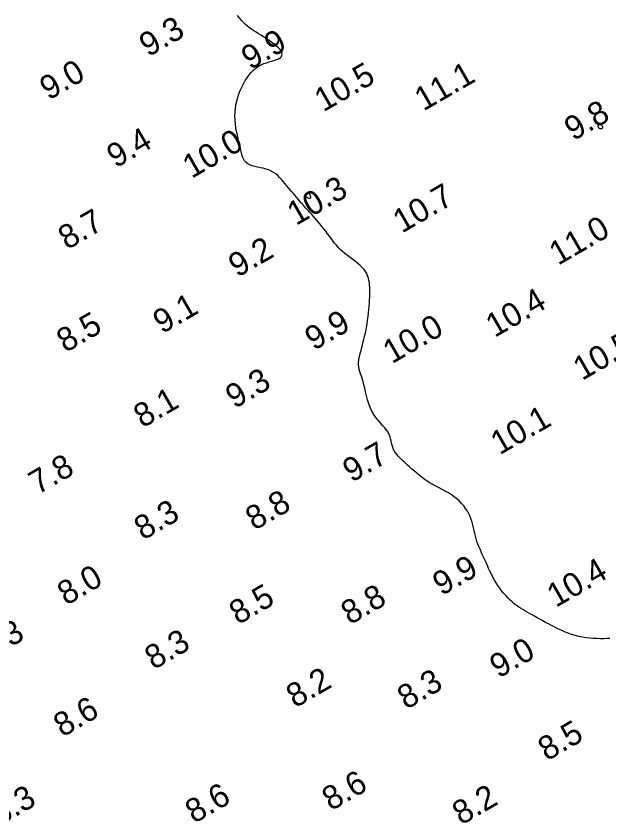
# Model space of a CAD drawing. Extents: x 3024098 to 3056816, y 418252 to 509144.
# Drawn here: x 3029994.4 to 3030119.4, y 418627.8 to 418798.2 of the extents above; entities that cross this region are included whole.
import ezdxf

# ---------------------------------------------------------------- set-up
doc = ezdxf.new("R2010")
doc.units = 0
doc.layers.add('V-CHAN-CONT-EL10', color=7, linetype='Continuous')
doc.layers.add('V-TOPO-SOUN-0911', color=7, linetype='Continuous')

msp = doc.modelspace()

# ---------------------------------------------------------------- linework, layer by layer
at = {"layer": 'V-CHAN-CONT-EL10'}
msp.add_lwpolyline([(3030119.56, 418666.92), (3030118.96, 418666.9), (3030118.31, 418666.89), (3030117.62, 418666.89), (3030116.9, 418666.9), (3030116.15, 418666.93), (3030115.39, 418666.99), (3030114.61, 418667.08), (3030113.82, 418667.19), (3030113.04, 418667.35), (3030112.27, 418667.55), (3030111.52, 418667.78), (3030110.77, 418668.05), (3030110.04, 418668.34), (3030109.33, 418668.66), (3030108.63, 418668.98), (3030107.95, 418669.32), (3030107.29, 418669.66), (3030106.64, 418669.99), (3030106.02, 418670.33), (3030105.42, 418670.66), (3030104.83, 418670.98), (3030104.26, 418671.29), (3030103.71, 418671.6), (3030103.18, 418671.9), (3030102.67, 418672.19), (3030102.17, 418672.48), (3030101.69, 418672.75), (3030101.21, 418673.03), (3030100.75, 418673.32), (3030100.3, 418673.61), (3030099.85, 418673.93), (3030099.4, 418674.27), (3030098.96, 418674.65), (3030098.51, 418675.05), (3030098.06, 418675.49), (3030097.62, 418675.96), (3030097.19, 418676.46), (3030096.76, 418676.98), (3030096.36, 418677.52), (3030095.96, 418678.09), (3030095.59, 418678.67), (3030095.25, 418679.26), (3030094.92, 418679.87), (3030094.61, 418680.48), (3030094.31, 418681.1), (3030094.03, 418681.71), (3030093.76, 418682.32), (3030093.49, 418682.92), (3030093.23, 418683.51), (3030092.96, 418684.09), (3030092.7, 418684.65), (3030092.45, 418685.2), (3030092.21, 418685.75), (3030091.97, 418686.3), (3030091.76, 418686.84), (3030091.56, 418687.4), (3030091.39, 418687.96), (3030091.23, 418688.53), (3030091.1, 418689.1), (3030090.97, 418689.69), (3030090.83, 418690.28), (3030090.69, 418690.87), (3030090.53, 418691.46), (3030090.35, 418692.05), (3030090.12, 418692.64), (3030089.85, 418693.22), (3030089.54, 418693.78), (3030089.18, 418694.34), (3030088.78, 418694.88), (3030088.34, 418695.4), (3030087.86, 418695.9), (3030087.34, 418696.37), (3030086.78, 418696.82), (3030086.18, 418697.23), (3030085.55, 418697.62), (3030084.9, 418697.98), (3030084.24, 418698.34), (3030083.58, 418698.69), (3030082.92, 418699.03), (3030082.27, 418699.38), (3030081.64, 418699.74), (3030081.04, 418700.12), (3030080.47, 418700.51), (3030079.93, 418700.92), (3030079.39, 418701.34), (3030078.88, 418701.77), (3030078.37, 418702.2), (3030077.86, 418702.65), (3030077.35, 418703.1), (3030076.85, 418703.55), (3030076.34, 418704.01), (3030075.86, 418704.47), (3030075.39, 418704.93), (3030074.97, 418705.39), (3030074.58, 418705.85), (3030074.26, 418706.31), (3030073.99, 418706.76), (3030073.8, 418707.22), (3030073.66, 418707.67), (3030073.55, 418708.12), (3030073.46, 418708.57), (3030073.36, 418709.03), (3030073.24, 418709.48), (3030073.07, 418709.94), (3030072.83, 418710.41), (3030072.51, 418710.88), (3030072.13, 418711.36), (3030071.69, 418711.86), (3030071.22, 418712.39), (3030070.74, 418712.95), (3030070.27, 418713.55), (3030069.82, 418714.19), (3030069.41, 418714.89), (3030069.06, 418715.64), (3030068.76, 418716.44), (3030068.5, 418717.26), (3030068.28, 418718.09), (3030068.09, 418718.91), (3030067.91, 418719.69), (3030067.74, 418720.44), (3030067.57, 418721.12), (3030067.39, 418721.72), (3030067.21, 418722.26), (3030067.04, 418722.76), (3030066.89, 418723.23), (3030066.77, 418723.68), (3030066.68, 418724.15), (3030066.63, 418724.63), (3030066.63, 418725.16), (3030066.69, 418725.74), (3030066.81, 418726.37), (3030066.96, 418727.04), (3030067.14, 418727.76), (3030067.34, 418728.51), (3030067.54, 418729.28), (3030067.75, 418730.07), (3030067.94, 418730.87), (3030068.12, 418731.68), (3030068.27, 418732.49), (3030068.4, 418733.29), (3030068.52, 418734.08), (3030068.62, 418734.86), (3030068.7, 418735.61), (3030068.78, 418736.33), (3030068.84, 418737.02), (3030068.9, 418737.67), (3030068.94, 418738.29), (3030068.98, 418738.88), (3030069.01, 418739.43), (3030069.02, 418739.97), (3030069.01, 418740.49), (3030068.99, 418740.99), (3030068.95, 418741.48), (3030068.89, 418741.97), (3030068.8, 418742.45), (3030068.68, 418742.93), (3030068.52, 418743.4), (3030068.32, 418743.86), (3030068.07, 418744.31), (3030067.76, 418744.75), (3030067.39, 418745.19), (3030066.96, 418745.61), (3030066.47, 418746.03), (3030065.94, 418746.44), (3030065.39, 418746.84), (3030064.83, 418747.25), (3030064.27, 418747.67), (3030063.73, 418748.08), (3030063.22, 418748.51), (3030062.75, 418748.95), (3030062.32, 418749.39), (3030061.93, 418749.85), (3030061.55, 418750.32), (3030061.19, 418750.8), (3030060.83, 418751.28), (3030060.46, 418751.78), (3030060.09, 418752.29), (3030059.7, 418752.8), (3030059.29, 418753.31), (3030058.87, 418753.83), (3030058.44, 418754.35), (3030058.01, 418754.86), (3030057.58, 418755.35), (3030057.16, 418755.84), (3030056.75, 418756.31), (3030056.35, 418756.76), (3030055.97, 418757.19), (3030055.6, 418757.61), (3030055.23, 418758.01), (3030054.88, 418758.41), (3030054.53, 418758.8), (3030054.19, 418759.2), (3030053.85, 418759.59), (3030053.51, 418759.99), (3030053.17, 418760.4), (3030052.83, 418760.81), (3030052.49, 418761.22), (3030052.15, 418761.64), (3030051.8, 418762.05), (3030051.45, 418762.48), (3030051.1, 418762.9), (3030050.74, 418763.32), (3030050.37, 418763.74), (3030049.98, 418764.14), (3030049.58, 418764.53), (3030049.16, 418764.89), (3030048.7, 418765.21), (3030048.21, 418765.5), (3030047.69, 418765.74), (3030047.12, 418765.93), (3030046.53, 418766.08), (3030045.93, 418766.21), (3030045.33, 418766.33), (3030044.74, 418766.45), (3030044.19, 418766.6), (3030043.69, 418766.78), (3030043.26, 418767.01), (3030042.89, 418767.29), (3030042.6, 418767.64), (3030042.36, 418768.05), (3030042.16, 418768.51), (3030041.99, 418769.02), (3030041.84, 418769.59), (3030041.7, 418770.2), (3030041.56, 418770.85), (3030041.4, 418771.55), (3030041.23, 418772.28), (3030041.06, 418773.04), (3030040.91, 418773.83), (3030040.77, 418774.63), (3030040.66, 418775.45), (3030040.58, 418776.26), (3030040.55, 418777.08), (3030040.57, 418777.89), (3030040.64, 418778.69), (3030040.76, 418779.48), (3030040.92, 418780.26), (3030041.13, 418781.03), (3030041.38, 418781.78), (3030041.66, 418782.51), (3030041.98, 418783.22), (3030042.33, 418783.9), (3030042.72, 418784.56), (3030043.13, 418785.19), (3030043.57, 418785.78), (3030044.03, 418786.32), (3030044.52, 418786.81), (3030045.03, 418787.24), (3030045.56, 418787.61), (3030046.1, 418787.91), (3030046.65, 418788.15), (3030047.2, 418788.35), (3030047.74, 418788.51), (3030048.25, 418788.65), (3030048.73, 418788.79), (3030049.17, 418788.92), (3030049.56, 418789.06), (3030049.89, 418789.23), (3030050.15, 418789.43), (3030050.34, 418789.65), (3030050.46, 418789.89), (3030050.49, 418790.16), (3030050.44, 418790.45), (3030050.3, 418790.77), (3030050.07, 418791.11), (3030049.74, 418791.47), (3030049.32, 418791.85), (3030048.85, 418792.24), (3030048.32, 418792.63), (3030047.75, 418793.03), (3030047.18, 418793.41), (3030046.6, 418793.78), (3030046.04, 418794.13), (3030045.51, 418794.46), (3030045.01, 418794.77), (3030044.53, 418795.07), (3030044.08, 418795.38), (3030043.64, 418795.69), (3030043.21, 418796.03), (3030042.79, 418796.41), (3030042.38, 418796.82), (3030041.96, 418797.28), (3030041.54, 418797.79), (3030041.12, 418798.33)], dxfattribs=at)
for points in [[(3030117.82, 418774.46), (3030117.84, 418774.46), (3030117.85, 418774.47), (3030117.87, 418774.47), (3030117.89, 418774.47), (3030117.92, 418774.48), (3030117.94, 418774.49), (3030117.96, 418774.51), (3030117.99, 418774.53), (3030118.01, 418774.55), (3030118.04, 418774.58), (3030118.06, 418774.61), (3030118.08, 418774.64), (3030118.09, 418774.67), (3030118.1, 418774.71), (3030118.1, 418774.74), (3030118.09, 418774.78), (3030118.07, 418774.82), (3030118.04, 418774.86), (3030118.02, 418774.9), (3030117.98, 418774.94), (3030117.95, 418774.99), (3030117.92, 418775.04), (3030117.88, 418775.1), (3030117.85, 418775.16), (3030117.82, 418775.23), (3030117.79, 418775.29), (3030117.76, 418775.35), (3030117.73, 418775.41), (3030117.7, 418775.46), (3030117.67, 418775.5), (3030117.63, 418775.53), (3030117.59, 418775.54), (3030117.55, 418775.54), (3030117.5, 418775.53), (3030117.46, 418775.51), (3030117.41, 418775.49), (3030117.37, 418775.45), (3030117.32, 418775.41), (3030117.28, 418775.37), (3030117.24, 418775.33), (3030117.2, 418775.28), (3030117.17, 418775.23), (3030117.14, 418775.18), (3030117.12, 418775.13), (3030117.1, 418775.07), (3030117.09, 418775.02), (3030117.08, 418774.96), (3030117.08, 418774.9), (3030117.1, 418774.85), (3030117.11, 418774.79), (3030117.14, 418774.73), (3030117.16, 418774.68), (3030117.19, 418774.64), (3030117.23, 418774.6), (3030117.27, 418774.56), (3030117.31, 418774.54), (3030117.36, 418774.52), (3030117.4, 418774.5), (3030117.45, 418774.49), (3030117.5, 418774.48), (3030117.54, 418774.48), (3030117.58, 418774.48), (3030117.62, 418774.48), (3030117.65, 418774.48), (3030117.68, 418774.48), (3030117.71, 418774.48), (3030117.73, 418774.47), (3030117.75, 418774.47), (3030117.77, 418774.47), (3030117.78, 418774.47), (3030117.8, 418774.47)], [(3030056.49, 418759.85), (3030056.52, 418759.91), (3030056.53, 418759.98), (3030056.52, 418760.06), (3030056.51, 418760.14), (3030056.48, 418760.23), (3030056.45, 418760.31), (3030056.42, 418760.38), (3030056.38, 418760.45), (3030056.35, 418760.51), (3030056.31, 418760.57), (3030056.27, 418760.61), (3030056.23, 418760.65), (3030056.19, 418760.69), (3030056.14, 418760.73), (3030056.09, 418760.76), (3030056.03, 418760.79), (3030055.96, 418760.82), (3030055.9, 418760.84), (3030055.83, 418760.85), (3030055.76, 418760.85), (3030055.7, 418760.85), (3030055.64, 418760.82), (3030055.59, 418760.78), (3030055.54, 418760.72), (3030055.51, 418760.64), (3030055.49, 418760.55), (3030055.48, 418760.45), (3030055.49, 418760.35), (3030055.51, 418760.25), (3030055.56, 418760.15), (3030055.62, 418760.06), (3030055.71, 418759.98), (3030055.81, 418759.91), (3030055.92, 418759.85), (3030056.04, 418759.81), (3030056.16, 418759.79), (3030056.27, 418759.78), (3030056.36, 418759.79), (3030056.44, 418759.81)]]:
    msp.add_lwpolyline(points, close=True, dxfattribs=at)

# ---------------------------------------------------------------- texts
at = {"layer": 'V-TOPO-SOUN-0911'}
for s, p in [('9.3', (3030022.27, 418789.45)), ('9.9', (3030043.79, 418786.73)), ('9.0', (3030001.29, 418780.33)), ('10.5 ', (3030059.2, 418777.86)), ('11.1 ', (3030080.29, 418778.04)), ('9.8', (3030111.87, 418771.77)), ('9.4', (3030015.41, 418766.02)), ('10.0 ', (3030031.41, 418763.82)), ('10.3 ', (3030053.44, 418753.91)), ('10.7 ', (3030075.75, 418752.3)), ('8.7', (3030005.18, 418748.8)), ('11.0 ', (3030108.67, 418745.51)), ('9.2', (3030041.07, 418742.96)), ('10.4 ', (3030095.3, 418730.29)), ('9.1', (3030025.17, 418731.07)), ('8.5', (3030004.84, 418727.11)), ('9.9', (3030057.18, 418727.54)), ('10.0 ', (3030073.63, 418724.74)), ('10.5 ', (3030113.73, 418721.23)), ('9.3', (3030040.45, 418715.3)), ('8.1', (3030021.07, 418711.22)), ('10.1 ', (3030096.34, 418705.53)), ('9.7', (3030065.15, 418699.72)), ('7.8', (3029998.98, 418697.16)), ('8.8', (3030044.65, 418689.61)), ('8.3', (3030021.19, 418687.55)), ('9.9', (3030084.11, 418675.83)), ('10.4 ', (3030108.2, 418673.37)), ('8.0', (3030005, 418673.8)), ('8.5', (3030041.22, 418669.73)), ('8.8', (3030064.79, 418669.7)), ('8.3', (3029988.48, 418662.28)), ('8.3', (3030023.42, 418660.25)), ('9.0', (3030096.14, 418658.44)), ('8.2', (3030053.24, 418652.18)), ('8.3', (3030076.67, 418651.85)), ('8.6', (3030004.19, 418646.02)), ('8.5', (3030106.32, 418640.99)), ('8.6', (3030060.79, 418630.47)), ('8.3', (3029990.94, 418627.34)), ('8.6', (3030031.95, 418627.81)), ('8.2', (3030088.25, 418627.47))]:
    msp.add_text(s, height=5, rotation=30, dxfattribs=at).set_placement(p)

doc.saveas('drawing.dxf')
